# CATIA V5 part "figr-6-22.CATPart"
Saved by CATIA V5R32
Part number: Part1
Bounding box of the stored display mesh (mm): x 0 to 150, y -70 to 70, z -150 to 69.804
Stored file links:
  D:\PROJECTS\Project 2022\CATIA V5 6R 2022\Resources\Part Files\c06_catia_v5_6r2022_prt\figr-6-22.CATPart
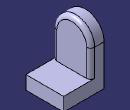
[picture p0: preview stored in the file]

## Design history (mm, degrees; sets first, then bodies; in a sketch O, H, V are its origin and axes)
Body1 (main body)
  Sketch1 on yz-plane, origin (0, 0, 0), H (0, 1, 0), V (0, 0, 1)
    arc A1 centre (0, 0) radius 70 from (70, 0) to (-70, 0) ccw
    point P1 (70, 0)
    point P2 (-70, 0)
    line L1 (-70, 0) -> (-70, -150)
    line L2 (-70, -150) -> (70, -150)
    line L3 (70, -150) -> (70, 0)
    construction circle A2 centre (0, 0) radius 37.5
    radius A1 = 70
    radius A2 = 37.5
    distance O L2 = 150
    coincidence: P1 H, P2 H
    tangency: L1 A1, L3 A1
    horizontal: L2 H
  Pad1: profile Sketch1, direction (1, 0, 0), length 50
  Sketch2 on face of Pad1, origin (50, 0, 0), H (0, 1, 0), V (0, 0, 1)
    line L1 (-70, -150) -> (70, -150)
    line L2 (70, -150) -> (70, -100)
    line L3 (70, -100) -> (-70, -100)
    line L4 (-70, -100) -> (-70, -150)
    reference projected line E1 (-70, -150) -> (70, -150) from edge [face of Pad1 | face of Pad1]
    reference projected line E2 (-70, 0) -> (-70, -150) from edge [face of Pad1 | face of Pad1]
    reference projected line E3 (70, -150) -> (70, 0) from edge [face of Pad1 | face of Pad1]
    length L2 = 50
    horizontal: L1 H, L3 H
    vertical: L2 V, L4 V
    coincidence: L1 E1, E2 L4, L2 E3
  Pad2: profile Sketch2, direction (1, 0, 0), length 100
  Fillet1: radius 15, on edge [face of Pad2 | end face of Pad1]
